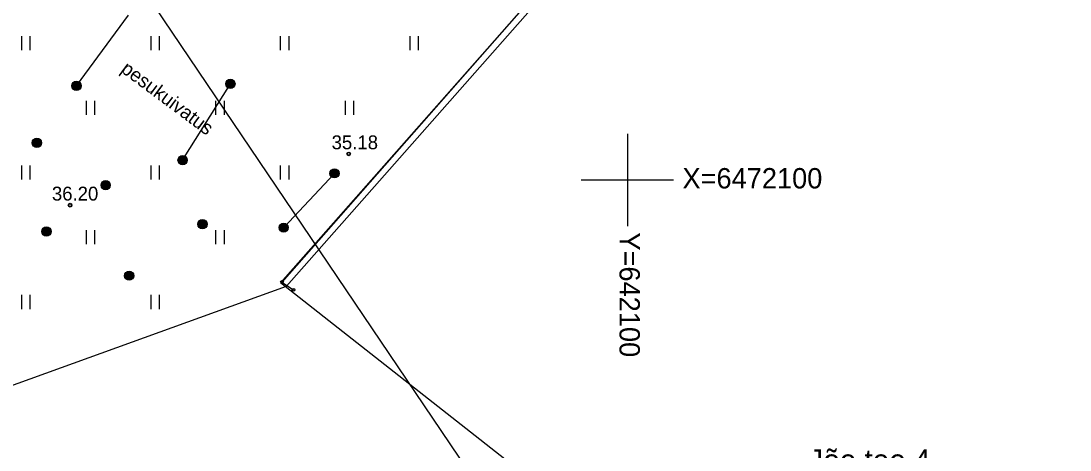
# Model space of a CAD drawing. Extents: x 641898 to 642452, y 6471715 to 6472255.
# Drawn here: x 642067.2 to 642123.9, y 6472085.4 to 6472108.6 of the extents above; entities that cross this region are included whole.
import ezdxf

# ---------------------------------------------------------------- set-up
doc = ezdxf.new("R2010")
doc.units = 0
for name, color, linetype in [('AED', 7, 'Continuous'), ('HALJASTUS', 7, 'Continuous'), ('KORGUS-EH2000', 7, 'Continuous'), ('MOOTMPUNKT', 7, 'Continuous'), ('MOOTPIIR', 7, 'Continuous'), ('MPOHULIIN', 7, 'Continuous'), ('PIIR', 7, 'Continuous'), ('RAJATIS', 7, 'Continuous'), ('VORK', 7, 'Continuous')]:
    doc.layers.add(name, color=color, linetype=linetype)

msp = doc.modelspace()

# ---------------------------------------------------------------- linework, layer by layer
at = {"layer": 'AED'}
msp.add_lwpolyline([(642123.481, 6472142.39), (642081.315, 6472094.482), (642081.931, 6472094.059)], dxfattribs=at)
at = {"layer": 'HALJASTUS'}
for p, q in [((642067.225, 6472107.782), (642067.225, 6472107.021)), ((642067.68, 6472107.782), (642067.68, 6472107.021)), ((642074.225, 6472107.782), (642074.225, 6472107.021)), ((642074.68, 6472107.782), (642074.68, 6472107.021)), ((642081.225, 6472107.782), (642081.225, 6472107.021)), ((642081.68, 6472107.782), (642081.68, 6472107.021)), ((642088.225, 6472107.782), (642088.225, 6472107.021)), ((642088.68, 6472107.782), (642088.68, 6472107.021)), ((642070.725, 6472104.282), (642070.725, 6472103.521)), ((642071.18, 6472104.282), (642071.18, 6472103.521)), ((642077.725, 6472104.282), (642077.725, 6472103.521)), ((642078.18, 6472104.282), (642078.18, 6472103.521)), ((642084.725, 6472104.282), (642084.725, 6472103.521)), ((642085.18, 6472104.282), (642085.18, 6472103.521)), ((642067.225, 6472100.782), (642067.225, 6472100.021)), ((642067.68, 6472100.782), (642067.68, 6472100.021)), ((642074.225, 6472100.782), (642074.225, 6472100.021)), ((642074.68, 6472100.782), (642074.68, 6472100.021)), ((642081.225, 6472100.782), (642081.225, 6472100.021)), ((642081.68, 6472100.782), (642081.68, 6472100.021)), ((642070.725, 6472097.282), (642070.725, 6472096.521)), ((642071.18, 6472097.282), (642071.18, 6472096.521)), ((642077.725, 6472097.282), (642077.725, 6472096.521)), ((642078.18, 6472097.282), (642078.18, 6472096.521)), ((642067.225, 6472093.782), (642067.225, 6472093.021)), ((642067.68, 6472093.782), (642067.68, 6472093.021)), ((642074.225, 6472093.782), (642074.225, 6472093.021)), ((642074.68, 6472093.782), (642074.68, 6472093.021))]:
    msp.add_line(p, q, dxfattribs=at)
at = {"layer": 'KORGUS-EH2000'}
for centre in [(642084.922, 6472101.409), (642069.852, 6472098.636)]:
    msp.add_circle(centre, 0.1, dxfattribs=at)
at = {"layer": 'MOOTMPUNKT'}
for centre in [(642084.922, 6472101.409), (642069.852, 6472098.636), (642081.315, 6472094.482), (642081.931, 6472094.059)]:
    msp.add_circle(centre, 0.075, dxfattribs=at)
at = {"layer": 'MOOTPIIR'}
msp.add_lwpolyline([(642014.306, 6472085.384), (642027.67, 6472104.979), (642055.501, 6472084.843), (642081.563, 6472094.262), (642123.938, 6472142.273), (642065.721, 6472244.475), (642008.922, 6472196.948), (642003.347, 6472200.453), (641979.65, 6472162.756), (641979.65, 6472162.756), (641986.045, 6472158.736), (642004.269, 6472142.365), (641987.048, 6472123.488), (641970.482, 6472097.889), (641986.758, 6472084.396)], close=True, dxfattribs=at)
at = {"layer": 'MPOHULIIN'}
msp.add_lwpolyline([(642026.721, 6472180.493), (642057.005, 6472135.15), (642092.759, 6472082.232), (642082.032, 6472055.789), (642066.817, 6472023.473)], dxfattribs=at)
at = {"layer": 'PIIR'}
for p, q in [((642081.23, 6472094.44), (642123.61, 6472142.4)), ((642111.934, 6472070.343), (642081.23, 6472094.44))]:
    msp.add_line(p, q, dxfattribs=at)
at = {"layer": 'RAJATIS'}
for points in [[(642070.197, 6472105.087), (642073.013, 6472108.908)], [(642075.94, 6472101.071), (642078.524, 6472105.193)], [(642081.408, 6472097.421), (642084.157, 6472100.356)]]:
    msp.add_lwpolyline(points, dxfattribs=at)
for centre, radius in [((642070.197, 6472105.087), 0.25), ((642070.197, 6472105.087), 0.225), ((642070.197, 6472105.087), 0.2), ((642078.524, 6472105.193), 0.25), ((642078.524, 6472105.193), 0.225), ((642078.524, 6472105.193), 0.2), ((642078.524, 6472105.193), 0.175), ((642078.524, 6472105.193), 0.15), ((642078.524, 6472105.193), 0.125), ((642078.524, 6472105.193), 0.1), ((642070.197, 6472105.087), 0.175), ((642070.197, 6472105.087), 0.15), ((642070.197, 6472105.087), 0.125), ((642070.197, 6472105.087), 0.1), ((642070.197, 6472105.087), 0.075), ((642070.197, 6472105.087), 0.05), ((642070.197, 6472105.087), 0.025), ((642078.524, 6472105.193), 0.075), ((642078.524, 6472105.193), 0.05), ((642078.524, 6472105.193), 0.025), ((642068.059, 6472102.01), 0.25), ((642068.059, 6472102.01), 0.225), ((642068.059, 6472102.01), 0.2), ((642068.059, 6472102.01), 0.175), ((642068.059, 6472102.01), 0.15), ((642068.059, 6472102.01), 0.125), ((642068.059, 6472102.01), 0.1), ((642068.059, 6472102.01), 0.075), ((642068.059, 6472102.01), 0.05), ((642068.059, 6472102.01), 0.025), ((642075.94, 6472101.071), 0.25), ((642075.94, 6472101.071), 0.225), ((642075.94, 6472101.071), 0.2), ((642075.94, 6472101.071), 0.175), ((642075.94, 6472101.071), 0.15), ((642075.94, 6472101.071), 0.125), ((642075.94, 6472101.071), 0.1), ((642075.94, 6472101.071), 0.075), ((642075.94, 6472101.071), 0.05), ((642075.94, 6472101.071), 0.025), ((642084.157, 6472100.356), 0.25), ((642084.157, 6472100.356), 0.225), ((642084.157, 6472100.356), 0.2), ((642084.157, 6472100.356), 0.175), ((642084.157, 6472100.356), 0.15), ((642084.157, 6472100.356), 0.125), ((642084.157, 6472100.356), 0.1), ((642084.157, 6472100.356), 0.075), ((642084.157, 6472100.356), 0.05), ((642084.157, 6472100.356), 0.025), ((642071.779, 6472099.716), 0.25), ((642071.779, 6472099.716), 0.225), ((642071.779, 6472099.716), 0.2), ((642071.779, 6472099.716), 0.175), ((642071.779, 6472099.716), 0.15), ((642071.779, 6472099.716), 0.125), ((642071.779, 6472099.716), 0.1), ((642071.779, 6472099.716), 0.075), ((642071.779, 6472099.716), 0.05), ((642071.779, 6472099.716), 0.025), ((642068.575, 6472097.212), 0.25), ((642068.575, 6472097.212), 0.225), ((642068.575, 6472097.212), 0.2), ((642068.575, 6472097.212), 0.175), ((642068.575, 6472097.212), 0.15), ((642077.013, 6472097.605), 0.25), ((642077.013, 6472097.605), 0.225), ((642077.013, 6472097.605), 0.2), ((642077.013, 6472097.605), 0.175), ((642077.013, 6472097.605), 0.15), ((642077.013, 6472097.605), 0.125), ((642077.013, 6472097.605), 0.1), ((642077.013, 6472097.605), 0.075), ((642077.013, 6472097.605), 0.05), ((642077.013, 6472097.605), 0.025), ((642081.408, 6472097.421), 0.25), ((642081.408, 6472097.421), 0.225), ((642081.408, 6472097.421), 0.2), ((642081.408, 6472097.421), 0.175), ((642081.408, 6472097.421), 0.15), ((642081.408, 6472097.421), 0.125), ((642081.408, 6472097.421), 0.1), ((642081.408, 6472097.421), 0.075), ((642081.408, 6472097.421), 0.05), ((642081.408, 6472097.421), 0.025), ((642068.575, 6472097.212), 0.125), ((642068.575, 6472097.212), 0.1), ((642068.575, 6472097.212), 0.075), ((642068.575, 6472097.212), 0.05), ((642068.575, 6472097.212), 0.025), ((642073.05, 6472094.824), 0.25), ((642073.05, 6472094.824), 0.225), ((642073.05, 6472094.824), 0.2), ((642073.05, 6472094.824), 0.175), ((642073.05, 6472094.824), 0.15), ((642073.05, 6472094.824), 0.125), ((642073.05, 6472094.824), 0.1), ((642073.05, 6472094.824), 0.075), ((642073.05, 6472094.824), 0.05), ((642073.05, 6472094.824), 0.025)]:
    msp.add_circle(centre, radius, dxfattribs=at)
at = {"layer": 'VORK'}
for p, q in [((642100, 6472102.5), (642100, 6472097.5)), ((642097.5, 6472100), (642102.5, 6472100))]:
    msp.add_line(p, q, dxfattribs=at)

# ---------------------------------------------------------------- texts
at = {"layer": 'KORGUS-EH2000'}
for s, p in [('35.18', (642083.999, 6472101.659)), ('36.20', (642068.87, 6472098.886))]:
    msp.add_text(s, height=0.75, dxfattribs=at).set_placement(p)
at = {"layer": 'PIIR'}
msp.add_text('Jõe tee 4', height=1.2, dxfattribs=at).set_placement((642109.79, 6472084.238))
at = {"layer": 'RAJATIS'}
msp.add_text('pesukuivatus', height=0.75, rotation=323.3629, dxfattribs=at).set_placement((642072.55, 6472105.875))
at = {"layer": 'VORK'}
msp.add_text('X=6472100', height=1.1, dxfattribs=at).set_placement((642102.975, 6472099.542))
msp.add_text('Y=642100', height=1.1, rotation=270, dxfattribs=at).set_placement((642099.571, 6472097.165))

doc.saveas('drawing.dxf')
